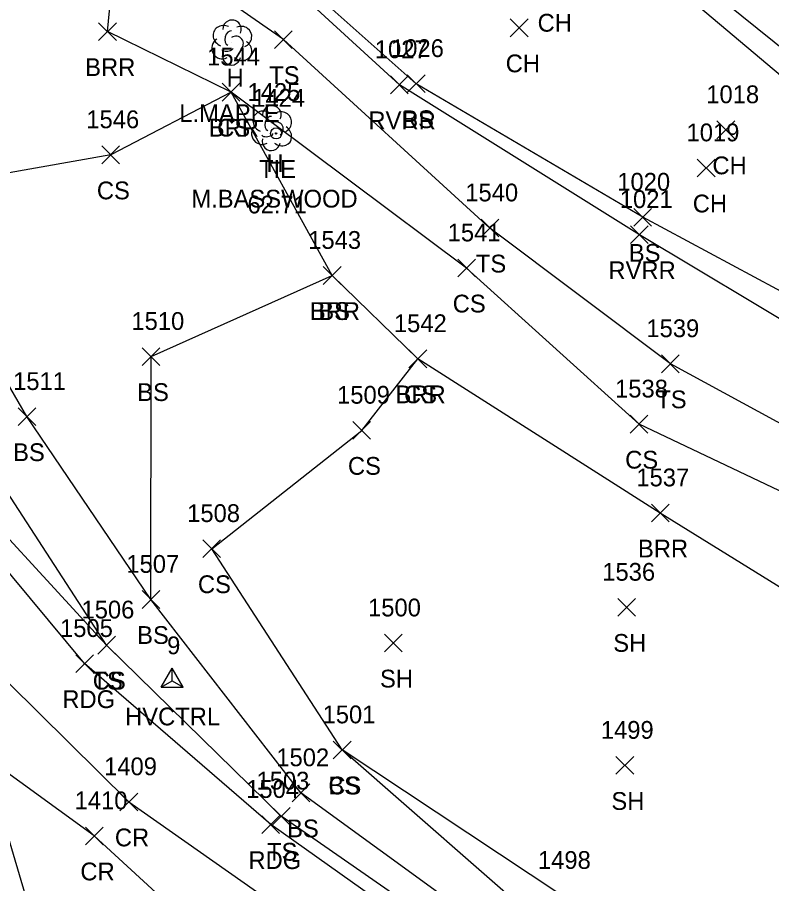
# Model space of a CAD drawing. Extents: x 1469310 to 1475157, y 493997 to 498873.
# Drawn here: x 1469623 to 1469708, y 498476.8 to 498574.2 of the extents above; entities that cross this region are included whole.
import ezdxf

# ---------------------------------------------------------------- set-up
doc = ezdxf.new("R2010")
doc.units = 0
for name, color, linetype in [('C_A', 7, 'Continuous'), ('C_C', 7, 'Continuous'), ('C_I', 7, 'Continuous'), ('CBP', 7, 'Continuous'), ('CPSM', 7, 'Continuous'), ('L_A', 7, 'Continuous'), ('L_C', 7, 'Continuous'), ('L_I', 7, 'Continuous'), ('L_TIC', 7, 'Continuous'), ('LABL', 7, 'Continuous'), ('LAWE', 7, 'Continuous'), ('LELB', 7, 'Continuous'), ('LTD', 7, 'Continuous'), ('P_A', 7, 'Continuous'), ('P_I', 7, 'Continuous'), ('P_TIC', 7, 'Continuous'), ('PEU', 7, 'Continuous'), ('PRC', 7, 'Continuous')]:
    doc.layers.add(name, color=color, linetype=linetype)

msp = doc.modelspace()

# ---------------------------------------------------------------- linework, layer by layer
at = {"layer": 'CBP'}
for radius in [0.625, 0.0833]:
    msp.add_circle((1469652.181, 498561.18), radius, dxfattribs=at)
at = {"layer": 'CPSM'}
for p, q in [((1469639.233, 498498.852), (1469640.483, 498501.017)), ((1469641.733, 498498.852), (1469640.483, 498501.017)), ((1469640.483, 498499.573), (1469640.483, 498501.017)), ((1469639.233, 498498.852), (1469640.483, 498499.573)), ((1469640.483, 498499.573), (1469640.483, 498499.573)), ((1469640.483, 498499.573), (1469641.733, 498498.852)), ((1469639.233, 498498.852), (1469641.733, 498498.852))]:
    msp.add_line(p, q, dxfattribs=at)
at = {"layer": 'L_TIC'}
for points in [[(1469632.195, 498571.637), (1469634.195, 498573.637)], [(1469634.195, 498571.637), (1469632.195, 498573.637)], [(1469678.538, 498572.06), (1469680.538, 498574.06)], [(1469680.538, 498572.06), (1469678.538, 498574.06)], [(1469651.996, 498570.738), (1469653.996, 498572.738)], [(1469653.996, 498570.738), (1469651.996, 498572.738)], [(1469646.104, 498564.825), (1469648.104, 498566.825)], [(1469648.104, 498564.825), (1469646.104, 498566.825)], [(1469646.104, 498564.825), (1469648.104, 498566.825)], [(1469648.104, 498564.825), (1469646.104, 498566.825)], [(1469665.06, 498565.648), (1469667.06, 498567.648)], [(1469667.06, 498565.648), (1469665.06, 498567.648)], [(1469666.941, 498565.775), (1469668.941, 498567.775)], [(1469668.941, 498565.775), (1469666.941, 498567.775)], [(1469701.811, 498560.583), (1469703.811, 498562.583)], [(1469703.811, 498560.583), (1469701.811, 498562.583)], [(1469632.561, 498557.766), (1469634.561, 498559.766)], [(1469634.561, 498557.766), (1469632.561, 498559.766)], [(1469699.597, 498556.292), (1469701.597, 498558.292)], [(1469701.597, 498556.292), (1469699.597, 498558.292)], [(1469692.445, 498550.74), (1469694.445, 498552.74)], [(1469694.445, 498550.74), (1469692.445, 498552.74)], [(1469675.255, 498549.532), (1469677.255, 498551.532)], [(1469677.255, 498549.532), (1469675.255, 498551.532)], [(1469692.077, 498548.784), (1469694.077, 498550.784)], [(1469694.077, 498548.784), (1469692.077, 498550.784)], [(1469672.62, 498545.033), (1469674.62, 498547.033)], [(1469674.62, 498545.033), (1469672.62, 498547.033)], [(1469657.486, 498544.191), (1469659.486, 498546.191)], [(1469659.486, 498544.191), (1469657.486, 498546.191)], [(1469657.486, 498544.191), (1469659.486, 498546.191)], [(1469659.486, 498544.191), (1469657.486, 498546.191)], [(1469637.101, 498535.07), (1469639.101, 498537.07)], [(1469639.101, 498535.07), (1469637.101, 498537.07)], [(1469667.132, 498534.818), (1469669.132, 498536.818)], [(1469669.132, 498534.818), (1469667.132, 498536.818)], [(1469667.132, 498534.818), (1469669.132, 498536.818)], [(1469669.132, 498534.818), (1469667.132, 498536.818)], [(1469695.566, 498534.255), (1469697.566, 498536.255)], [(1469697.566, 498534.255), (1469695.566, 498536.255)], [(1469623.13, 498528.309), (1469625.13, 498530.309)], [(1469625.13, 498528.309), (1469623.13, 498530.309)], [(1469692.032, 498527.464), (1469694.032, 498529.464)], [(1469694.032, 498527.464), (1469692.032, 498529.464)], [(1469660.822, 498526.768), (1469662.822, 498528.768)], [(1469662.822, 498526.768), (1469660.822, 498528.768)], [(1469694.428, 498517.468), (1469696.428, 498519.468)], [(1469696.428, 498517.468), (1469694.428, 498519.468)], [(1469643.936, 498513.452), (1469645.936, 498515.452)], [(1469645.936, 498513.452), (1469643.936, 498515.452)], [(1469637.094, 498507.736), (1469639.094, 498509.736)], [(1469639.094, 498507.736), (1469637.094, 498509.736)], [(1469637.094, 498507.736), (1469639.094, 498509.736)], [(1469639.094, 498507.736), (1469637.094, 498509.736)], [(1469690.645, 498506.848), (1469692.645, 498508.848)], [(1469692.645, 498506.848), (1469690.645, 498508.848)], [(1469632.096, 498502.601), (1469634.096, 498504.601)], [(1469634.096, 498502.601), (1469632.096, 498504.601)], [(1469632.096, 498502.601), (1469634.096, 498504.601)], [(1469634.096, 498502.601), (1469632.096, 498504.601)], [(1469664.386, 498502.832), (1469666.386, 498504.832)], [(1469666.386, 498502.832), (1469664.386, 498504.832)], [(1469658.613, 498490.802), (1469660.613, 498492.802)], [(1469660.613, 498490.802), (1469658.613, 498492.802)], [(1469658.613, 498490.802), (1469660.613, 498492.802)], [(1469660.613, 498490.802), (1469658.613, 498492.802)], [(1469690.435, 498489.062), (1469692.435, 498491.062)], [(1469692.435, 498489.062), (1469690.435, 498491.062)], [(1469653.974, 498485.974), (1469655.974, 498487.974)], [(1469655.974, 498485.974), (1469653.974, 498487.974)], [(1469651.746, 498483.347), (1469653.746, 498485.347)], [(1469653.746, 498483.347), (1469651.746, 498485.347)]]:
    msp.add_lwpolyline(points, dxfattribs=at)
at = {"layer": 'LABL'}
msp.add_lwpolyline([(1469812.399, 498427.833), (1469789.823, 498450.509), (1469762.155, 498470.412), (1469730.759, 498496.59), (1469695.428, 498518.468), (1469668.132, 498535.818), (1469658.486, 498545.191), (1469647.104, 498565.825), (1469633.195, 498572.637), (1469634.36, 498584.722)], dxfattribs=at)
at = {"layer": 'LAWE'}
for points in [[(1469773.599, 498538.143), (1469743.152, 498547.619), (1469721.093, 498561.124), (1469693.491, 498583.351), (1469669.748, 498607.461), (1469645.136, 498621.402), (1469610.764, 498626.27), (1469594.257, 498621.311), (1469595.404, 498613.659), (1469596.705, 498614.177)], [(1469777.093, 498513.113), (1469746.487, 498519.646), (1469712.258, 498538.306), (1469693.077, 498549.784), (1469666.06, 498566.648), (1469651.931, 498579.614), (1469627.93, 498592.682), (1469614.452, 498590.358), (1469606.528, 498592.025), (1469606.275, 498594.975), (1469607.183, 498595.593)]]:
    msp.add_lwpolyline(points, dxfattribs=at)
at = {"layer": 'LELB'}
for points in [[(1469772.295, 498536.699), (1469742.731, 498545.987), (1469719.144, 498559.139), (1469691.198, 498582.668), (1469667.675, 498605.387), (1469646.545, 498618.868), (1469610.656, 498623.611), (1469596.02, 498618.19), (1469597.153, 498614.345), (1469602.07, 498605.375)], [(1469781.028, 498516.12), (1469746.539, 498524.213), (1469713.591, 498540.942), (1469693.445, 498551.74), (1469667.941, 498566.775), (1469651.721, 498581.21), (1469628.321, 498594.647), (1469613.889, 498590.693), (1469608.413, 498591.74), (1469608.455, 498595.925), (1469602.07, 498605.375)], [(1469812.464, 498502.377), (1469771.643, 498507.322), (1469742.885, 498510.086), (1469696.566, 498535.255), (1469676.255, 498550.532), (1469652.996, 498571.738), (1469634.36, 498584.722), (1469625.46, 498586.142), (1469614.784, 498575.789), (1469604.978, 498569.723)], [(1469810.96, 498484.608), (1469774.316, 498494.217), (1469741.099, 498505.67), (1469693.032, 498528.464), (1469673.62, 498546.033), (1469647.104, 498565.825), (1469633.561, 498558.766), (1469612.977, 498555.124)], [(1469633.096, 498503.601), (1469614.184, 498524.16), (1469603.368, 498544.316), (1469596.337, 498559.709)], [(1469788.816, 498394.717), (1469772.488, 498406.102), (1469747.629, 498424.648), (1469713.944, 498449.335), (1469681.325, 498467.824), (1469654.974, 498486.974), (1469638.094, 498508.736), (1469624.13, 498529.309), (1469618.927, 498538.232), (1469619.738, 498548.83)], [(1469787.64, 498392.56), (1469771.327, 498404.285), (1469746.147, 498422.386), (1469712.154, 498445.439), (1469680.508, 498465.063), (1469652.746, 498484.347), (1469633.096, 498503.601), (1469618.233, 498526.441), (1469608.669, 498544.385), (1469612.833, 498546.464)], [(1469638.094, 498508.736), (1469638.101, 498536.07), (1469658.486, 498545.191)], [(1469794.773, 498402.662), (1469777.726, 498412.127), (1469751.37, 498432.818), (1469719.332, 498456.428), (1469684.35, 498475.422), (1469659.613, 498491.802), (1469644.936, 498514.452), (1469661.822, 498527.768), (1469668.132, 498535.818)], [(1469791.558, 498399.113), (1469776.416, 498410.487), (1469750.483, 498428.297), (1469716.937, 498452.537), (1469682.842, 498471.479), (1469659.613, 498491.802)]]:
    msp.add_lwpolyline(points, dxfattribs=at)
at = {"layer": 'LTD'}
for p, q in [((1469647.167, 498571.456), (1469647.167, 498571.456)), ((1469647.167, 498571.456), (1469647.167, 498571.456)), ((1469651.653, 498561.838), (1469651.653, 498561.838)), ((1469651.653, 498561.838), (1469651.653, 498561.838))]:
    msp.add_line(p, q, dxfattribs=at)
for centre in [(1469647.214, 498572.89), (1469651.7, 498563.272)]:
    msp.add_arc(centre, 1.047, 335.52715, 180.95627, dxfattribs=at)
for centre, major_axis, ratio, start_param, end_param in [((1469646.376, 498572.123), (1.21, -0.512), 0.895232, 1.570796, 4.712389), ((1469646.959, 498571.914), (-0.208, -0.792), 0.645439, 3.141593, 6.283185), ((1469648.209, 498572.04), (-1.141, -0.483), 0.949671, 1.570796, 4.712389), ((1469646.084, 498570.748), (0.584, -1.042), 0.959034, 3.141593, 6.283185), ((1469647.668, 498571.29), (-0.5, 0.667), 0.989748, 3.141593, 6.283185), ((1469646.709, 498570.706), (-0.625, -0.083), 0.423636, 0, 3.141593), ((1469648.168, 498570.623), (-1.09, 0.792), 0.841452, 1.570796, 4.712389), ((1469647.168, 498569.956), (0.265, 1.061), 0.942809, 1.570796, 4.712389), ((1469650.861, 498562.504), (1.21, -0.512), 0.895232, 1.570796, 4.712389), ((1469651.445, 498562.296), (-0.208, -0.792), 0.645439, 3.141593, 6.283185), ((1469652.695, 498562.421), (-1.141, -0.483), 0.949671, 1.570796, 4.712389), ((1469650.57, 498561.129), (0.584, -1.042), 0.959034, 3.141593, 6.283185), ((1469652.153, 498561.671), (-0.5, 0.667), 0.989748, 3.141593, 6.283185), ((1469651.195, 498561.088), (-0.625, -0.083), 0.423636, 0, 3.141593), ((1469652.653, 498561.005), (-1.09, 0.792), 0.841452, 1.570796, 4.712389), ((1469651.653, 498560.338), (0.265, 1.061), 0.942809, 1.570796, 4.712389)]:
    msp.add_ellipse(centre, major_axis=major_axis, ratio=ratio, start_param=start_param, end_param=end_param, dxfattribs=at)
at = {"layer": 'P_TIC'}
for points in [[(1469629.626, 498500.518), (1469631.626, 498502.518)], [(1469631.626, 498500.518), (1469629.626, 498502.518)], [(1469634.594, 498484.96), (1469636.594, 498486.96)], [(1469636.594, 498484.96), (1469634.594, 498486.96)], [(1469650.576, 498482.407), (1469652.576, 498484.407)], [(1469652.576, 498482.407), (1469650.576, 498484.407)], [(1469630.711, 498481.132), (1469632.711, 498483.132)], [(1469632.711, 498481.132), (1469630.711, 498483.132)]]:
    msp.add_lwpolyline(points, dxfattribs=at)
at = {"layer": 'PEU'}
for points in [[(1469787.287, 498391.186), (1469770.786, 498403.186), (1469744.942, 498420.511), (1469711.225, 498443.774), (1469680.07, 498463.208), (1469651.576, 498483.407), (1469630.626, 498501.518), (1469612.52, 498523.24), (1469599.406, 498542.19), (1469591.57, 498556.602), (1469575.608, 498583.062), (1469557.307, 498607.493), (1469540.085, 498628.651), (1469536.237, 498634.985), (1469514.981, 498658.506), (1469490.833, 498684.266), (1469472.689, 498702.569), (1469444.888, 498732.157), (1469424.966, 498753.74), (1469411.282, 498767.744), (1469386.832, 498794.065), (1469360.465, 498820.438)], [(1469637.732, 498433.091), (1469628.78, 498459.194), (1469619.325, 498491.121), (1469611.933, 498509.329), (1469599.406, 498542.19)]]:
    msp.add_lwpolyline(points, dxfattribs=at)
at = {"layer": 'PRC'}
for points in [[(1469611.933, 498509.329), (1469635.594, 498485.96), (1469656.262, 498471.444), (1469676.231, 498459.148), (1469677.31, 498457.922), (1469704.762, 498441.376), (1469729.855, 498424.397), (1469757.525, 498405.578), (1469784.327, 498386.633)], [(1469631.711, 498482.132), (1469619.325, 498491.121)], [(1469631.711, 498482.132), (1469650.232, 498465.122), (1469670.398, 498454.477)]]:
    msp.add_lwpolyline(points, dxfattribs=at)

# ---------------------------------------------------------------- texts
at = {"layer": 'C_A'}
for s, p in [('TIE', (1469650.26, 498556.18)), ('HVCTRL', (1469635.176, 498494.573))]:
    msp.add_text(s, height=2, dxfattribs=at).set_placement(p)
at = {"layer": 'C_C'}
msp.add_text('62.71', height=2, dxfattribs=at).set_placement((1469648.953, 498552.18))
at = {"layer": 'C_I'}
for s, p in [('1424', (1469649.488, 498564.18)), ('9', (1469639.909, 498502.573))]:
    msp.add_text(s, height=2, dxfattribs=at).set_placement(p)
at = {"layer": 'L_A'}
for s, p in [('CH', (1469681.617, 498572.632)), ('CH', (1469678.026, 498568.06)), ('BRR', (1469630.683, 498567.637)), ('TS', (1469651.405, 498566.738)), ('H', (1469646.601, 498566.456)), ('RVRR', (1469662.572, 498561.648)), ('BS', (1469666.382, 498561.775)), ('BRR', (1469644.592, 498560.825)), ('CS', (1469645.545, 498560.825)), ('H', (1469651.086, 498556.838)), ('CH', (1469701.299, 498556.583)), ('CS', (1469632.002, 498553.766)), ('CH', (1469699.085, 498552.292)), ('BS', (1469691.886, 498546.74)), ('TS', (1469674.665, 498545.532)), ('RVRR', (1469689.589, 498544.784)), ('CS', (1469672.061, 498541.033)), ('BRR', (1469655.974, 498540.191)), ('BS', (1469656.927, 498540.191)), ('BS', (1469636.542, 498531.07)), ('BRR', (1469665.62, 498530.818)), ('CS', (1469666.573, 498530.818)), ('TS', (1469694.975, 498530.255)), ('BS', (1469622.571, 498524.309)), ('CS', (1469691.473, 498523.464)), ('CS', (1469660.263, 498522.768)), ('BRR', (1469692.916, 498513.468)), ('CS', (1469643.377, 498509.452)), ('BS', (1469636.535, 498503.736)), ('BS', (1469636.535, 498503.736)), ('SH', (1469690.133, 498502.848)), ('TS', (1469631.506, 498498.601)), ('CS', (1469631.537, 498498.601)), ('SH', (1469663.874, 498498.832)), ('CS', (1469658.054, 498486.802)), ('BS', (1469658.054, 498486.802)), ('SH', (1469689.923, 498485.062)), ('BS', (1469653.415, 498481.974)), ('TS', (1469651.156, 498479.347))]:
    msp.add_text(s, height=2, dxfattribs=at).set_placement(p)
at = {"layer": 'L_C'}
for s, p in [('L.MAPLE', (1469641.278, 498562.456)), ('M.BASSWOOD', (1469642.637, 498552.838))]:
    msp.add_text(s, height=2, dxfattribs=at).set_placement(p)
at = {"layer": 'L_I'}
for s, p in [('1026', (1469665.115, 498569.775)), ('1544', (1469644.411, 498568.825)), ('1544', (1469644.411, 498568.825)), ('1027', (1469663.289, 498569.648)), ('1425', (1469648.96, 498564.838)), ('1018', (1469700.606, 498564.583)), ('1546', (1469630.813, 498561.766)), ('1019', (1469698.384, 498560.292)), ('1020', (1469690.587, 498554.74)), ('1540', (1469673.476, 498553.532)), ('1021', (1469690.872, 498552.784)), ('1541', (1469671.494, 498549.033)), ('1543', (1469655.793, 498548.191)), ('1543', (1469655.793, 498548.191)), ('1510', (1469635.889, 498539.07)), ('1542', (1469665.439, 498538.818)), ('1542', (1469665.439, 498538.818)), ('1539', (1469693.865, 498538.255)), ('1511', (1469622.572, 498532.309)), ('1509', (1469659.042, 498530.768)), ('1538', (1469690.339, 498531.464)), ('1537', (1469692.735, 498521.468)), ('1508', (1469642.164, 498517.452)), ('1507', (1469635.322, 498511.736)), ('1507', (1469635.322, 498511.736)), ('1536', (1469688.897, 498510.848)), ('1506', (1469630.27, 498506.601)), ('1506', (1469630.27, 498506.601)), ('1500', (1469662.528, 498506.832)), ('1501', (1469657.409, 498494.802)), ('1501', (1469657.409, 498494.802)), ('1499', (1469688.735, 498493.062)), ('1502', (1469652.203, 498489.974)), ('1503', (1469649.975, 498487.347)), ('1498', (1469681.657, 498478.422))]:
    msp.add_text(s, height=2, dxfattribs=at).set_placement(p)
at = {"layer": 'P_A'}
for s, p in [('RDG', (1469628.114, 498496.518)), ('CR', (1469634.027, 498480.96)), ('RDG', (1469649.064, 498478.407)), ('CR', (1469630.144, 498477.132))]:
    msp.add_text(s, height=2, dxfattribs=at).set_placement(p)
at = {"layer": 'P_I'}
for s, p in [('1505', (1469627.854, 498504.518)), ('1409', (1469632.814, 498488.96)), ('1504', (1469648.805, 498486.407)), ('1410', (1469629.499, 498485.132))]:
    msp.add_text(s, height=2, dxfattribs=at).set_placement(p)

doc.saveas('drawing.dxf')
